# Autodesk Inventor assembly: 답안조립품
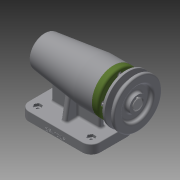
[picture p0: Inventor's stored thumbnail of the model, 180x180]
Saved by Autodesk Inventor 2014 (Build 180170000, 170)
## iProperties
Created: 2017-01
Part Number: 답안조립품
Document SubType Name: Assembly
Designer: user
Author: user
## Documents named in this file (12)
- C:\Users\user\Desktop\470108V1003\답안조립품.iam
- C:\Users\user\Desktop\470108V1003\본체.ipt
- C:\Users\user\Desktop\470108V1003\커버.ipt
- C:\Users\user\Desktop\470108V1003\볼트 M4 x 12.ipt
- C:\Users\user\Desktop\470108V1003\오일 실.ipt
- C:\Users\user\Desktop\470108V1003\베어링 6004.ipt
- C:\Users\user\Desktop\470108V1003\축.ipt
- C:\Users\user\Desktop\470108V1003\어댑터슬리브.ipt
- C:\Users\user\Desktop\470108V1003\베어링 51202.ipt
- C:\Users\user\Desktop\470108V1003\키 5 x 5 x 16.ipt
- C:\Users\user\Desktop\470108V1003\V벨트풀리.ipt
- C:\Users\user\Desktop\470108V1003\멈춤나사 M3x8.ipt
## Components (6 placed, 2 different names)
1. ISO 4762 M4 x 12:5
2. V벨트풀리:2
3. ISO 4762 M4 x 12:1
4. ISO 4762 M4 x 12:2
5. ISO 4762 M4 x 12:3
6. ISO 4762 M4 x 12:4
